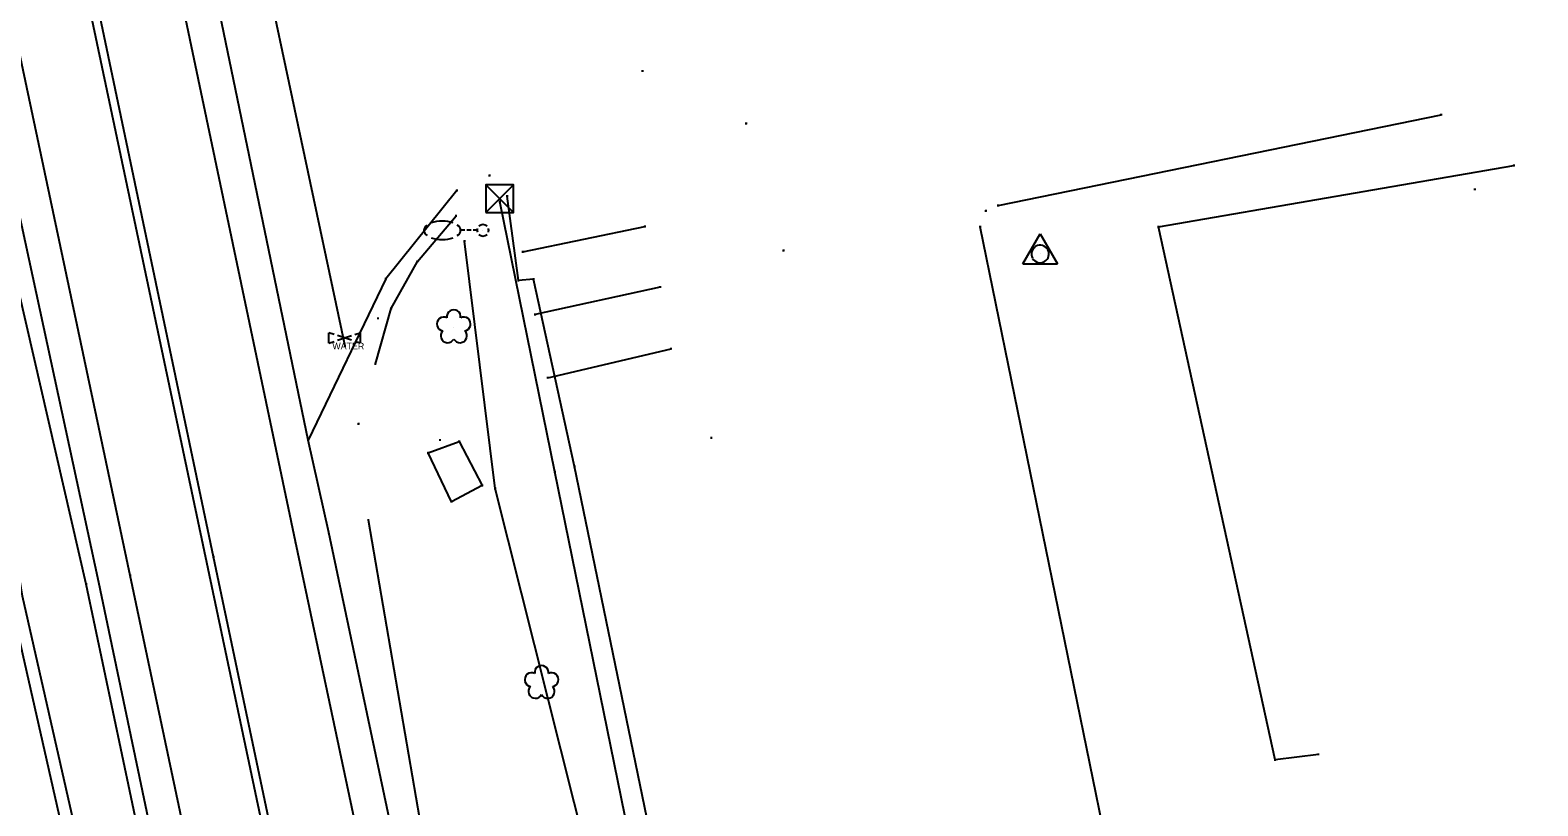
# Model space of a CAD drawing. Extents: x 1954856 to 2011933, y 399149 to 426294.
# Drawn here: x 2005902.3 to 2006119.2, y 403540.3 to 403651.8 of the extents above; entities that cross this region are included whole.
import ezdxf

# ---------------------------------------------------------------- set-up
doc = ezdxf.new("R2010")
doc.units = 0
for name, color, linetype in [('BankMent_ep', 7, 'Continuous'), ('BaselineSurvey', 7, 'Continuous'), ('Building_ep', 7, 'Continuous'), ('Driveway_ep', 7, 'Continuous'), ('Fence_ep', 7, 'Continuous'), ('Luminaire_ep', 7, 'Continuous'), ('MonumentIRC_ep', 7, 'Continuous'), ('MonumentPST_ep', 7, 'Continuous'), ('PavtAsphalt_ep', 7, 'Continuous'), ('PavtAsphaltCrown_ep', 7, 'Continuous'), ('PavtMisc_ep', 7, 'Continuous'), ('PMRK_ep', 7, 'Continuous'), ('PointLocator_ep', 7, 'Continuous'), ('ShldrPaved_ep', 7, 'Continuous'), ('Stairs_ep', 7, 'Continuous'), ('Tree_ep', 7, 'Continuous'), ('ValveWater_ep', 7, 'Continuous'), ('WaterB_ep', 7, 'Continuous')]:
    doc.layers.add(name, color=color, linetype=linetype)

msp = doc.modelspace()

# ---------------------------------------------------------------- linework, layer by layer
at = {"layer": 'BankMent_ep'}
for p, q in [((2005910.36, 403572.2), (2005893.93, 403643.41)), ((2005968.19, 403481.12), (2005950.95, 403581.41)), ((2005930.87, 403474.8), (2005910.36, 403572.2))]:
    msp.add_line(p, q, dxfattribs=at)
for points in [[(2006022.07, 402978.64), (2006021.6, 402982.93), (2006003.19, 403080.58), (2005983.54, 403176.28), (2005962.47, 403276.29), (2005940.44, 403373.6), (2005921.47, 403472.81), (2005899.51, 403569.73), (2005886.48, 403640.98)], [(2006026.18, 402980.46), (2006025.45, 402983.89), (2006004.8, 403080.94), (2005986.55, 403176.87), (2005964.79, 403276.97), (2005944.38, 403374.63), (2005923.28, 403472.99), (2005901.17, 403570.47), (2005889.78, 403641.66)], [(2006032.88, 403297.75), (2006007.75, 403389.93), (2005993.76, 403488.23), (2005969.18, 403585.92), (2005964.79, 403621.47)]]:
    msp.add_lwpolyline(points, dxfattribs=at)
at = {"layer": 'BaselineSurvey'}
msp.add_line((2006223.92, 402174.38), (2005094.48, 407516.05), dxfattribs=at)
msp.add_line((2006223.92, 402174.38), (2005094.48, 407516.05), dxfattribs=at)
at = {"layer": 'Building_ep'}
msp.add_lwpolyline([(2006087.61, 403547.72), (2006081.39, 403546.92), (2006064.61, 403623.54), (2006115.74, 403632.36)], dxfattribs=at)
at = {"layer": 'Driveway_ep'}
for p, q in [((2005963.68, 403628.76), (2005953.48, 403616.07)), ((2005972.53, 403615.83), (2005970.92, 403627.98)), ((2005953.48, 403616.07), (2005942.29, 403592.9)), ((2005974.72, 403616.02), (2005972.53, 403615.83)), ((2005980.62, 403589.11), (2005974.72, 403616.02)), ((2006000.9, 403490.61), (2005980.62, 403589.11))]:
    msp.add_line(p, q, dxfattribs=at)
at = {"layer": 'Fence_ep'}
msp.add_lwpolyline([(2005951.96, 403603.84), (2005954.23, 403611.8), (2005958.02, 403618.59), (2005963.56, 403625.11)], dxfattribs=at)
at = {"layer": 'Luminaire_ep'}
for p, q in [((2005964.81, 403623.05), (2005964.21, 403623.05)), ((2005965.71, 403623.05), (2005965.11, 403623.05)), ((2005966.61, 403623.05), (2005966.01, 403623.05)), ((2005967.43, 403623.05), (2005967.43, 403623.05))]:
    msp.add_line(p, q, dxfattribs=at)
for start, end in [(159.9115, 200.0885), (45, 135), (225, 315), (339.9115, 20.0885)]:
    msp.add_arc((2005967.43, 403623.05), 0.825, start, end, dxfattribs=at)
for start_param, end_param in [(4.075781, 5.348997), (5.668326, 6.898045), (2.526733, 3.756452), (0.934187, 2.207405)]:
    msp.add_ellipse((2005961.57, 403623.05), major_axis=(-2.64, 0), ratio=0.5, start_param=start_param, end_param=end_param, dxfattribs=at)
at = {"layer": 'MonumentIRC_ep'}
for p, q in [((2006045.09, 403618.21), (2006047.59, 403622.54)), ((2006047.59, 403622.54), (2006050.09, 403618.21)), ((2006045.09, 403618.21), (2006050.09, 403618.21)), ((2006047.59, 403619.65), (2006047.59, 403619.65))]:
    msp.add_line(p, q, dxfattribs=at)
msp.add_arc((2006047.59, 403619.65), 1.26, 209.9294, 209.03, dxfattribs=at)
at = {"layer": 'MonumentPST_ep'}
for p, q in [((2005967.84, 403629.6), (2005971.84, 403625.59)), ((2005967.84, 403625.59), (2005971.84, 403629.6)), ((2005969.84, 403627.6), (2005969.84, 403627.6))]:
    msp.add_line(p, q, dxfattribs=at)
msp.add_lwpolyline([(2005967.84, 403625.59), (2005971.84, 403625.59), (2005971.84, 403629.6), (2005967.84, 403629.6), (2005967.84, 403625.59)], dxfattribs=at)
at = {"layer": 'PavtAsphalt_ep'}
for p, q in [((2005916.68, 403573.45), (2005896.01, 403670.98)), ((2005937.3, 403476.2), (2005916.68, 403573.45))]:
    msp.add_line(p, q, dxfattribs=at)
msp.add_lwpolyline([(2006233.39, 402199.4), (2006231.31, 402208.78), (2006210.3, 402306.91), (2006189.73, 402404.41), (2006168.52, 402502.44), (2006147.45, 402600.55), (2006127, 402698.2), (2006106.48, 402795.48), (2006085.7, 402893.48), (2006064.78, 402991.32), (2006043.91, 403089.28), (2006023.05, 403187.5), (2006002.57, 403285.23), (2005981.7, 403382.7), (2005961.21, 403480.5), (2005940.45, 403578.3), (2005919.87, 403676.23), (2005898.84, 403774.26)], dxfattribs=at)
at = {"layer": 'PavtAsphaltCrown_ep'}
msp.add_lwpolyline([(2006221.58, 402197.04), (2006219.37, 402206.69), (2006198.42, 402304.43), (2006177.67, 402402.21), (2006156.49, 402500.14), (2006135.92, 402597.88), (2006115.39, 402695.49), (2006094.3, 402793.44), (2006073.8, 402891.43), (2006052.86, 402989.16), (2006032.08, 403086.96), (2006011.06, 403184.66), (2005990.58, 403282.63), (2005969.86, 403380.23), (2005949.3, 403478.33), (2005928.68, 403576.1), (2005908.1, 403674.03), (2005887.14, 403771.84)], dxfattribs=at)
at = {"layer": 'PavtMisc_ep'}
for p, q in [((2006041.53, 403626.6), (2006105.27, 403639.67)), ((2006041.53, 403626.6), (2006105.27, 403639.67)), ((2006058.94, 403525.92), (2006038.97, 403623.56)), ((2006058.94, 403525.92), (2006038.97, 403623.56))]:
    msp.add_line(p, q, dxfattribs=at)
at = {"layer": 'PMRK_ep'}
for points in [[(2005973.17, 403619.95), (2005990.73, 403623.59)], [(2005992.93, 403614.89), (2005974.93, 403610.93)], [(2005976.75, 403601.87), (2005994.49, 403606.03)]]:
    msp.add_lwpolyline(points, dxfattribs=at)
at = {"layer": 'PointLocator_ep'}
for p, q in [((2005990.5, 403645.95), (2005990.25, 403645.95)), ((2005990.37, 403645.83), (2005990.37, 403646.08)), ((2005990.37, 403645.95), (2005990.37, 403645.95)), ((2006105.39, 403639.67), (2006105.14, 403639.67)), ((2006105.27, 403639.54), (2006105.27, 403639.79)), ((2006105.27, 403639.67), (2006105.27, 403639.67)), ((2006005.42, 403638.39), (2006005.17, 403638.39)), ((2006005.29, 403638.27), (2006005.29, 403638.52)), ((2006005.29, 403638.39), (2006005.29, 403638.39)), ((2005968.39, 403630.79), (2005968.39, 403631.04)), ((2006115.86, 403632.36), (2006115.61, 403632.36)), ((2006115.74, 403632.23), (2006115.74, 403632.48)), ((2006115.74, 403632.36), (2006115.74, 403632.36)), ((2005963.81, 403628.76), (2005963.56, 403628.76)), ((2005963.68, 403628.64), (2005963.68, 403628.89)), ((2005963.68, 403628.76), (2005963.68, 403628.76)), ((2005968.52, 403630.91), (2005968.27, 403630.91)), ((2005968.39, 403630.91), (2005968.39, 403630.91)), ((2006110.26, 403628.92), (2006110.01, 403628.92)), ((2006110.13, 403628.8), (2006110.13, 403629.05)), ((2006110.13, 403628.92), (2006110.13, 403628.92)), ((2005970, 403627.19), (2005969.75, 403627.19)), ((2005969.88, 403627.07), (2005969.88, 403627.32)), ((2005969.88, 403627.19), (2005969.88, 403627.19)), ((2005971.05, 403627.98), (2005970.8, 403627.98)), ((2005970.92, 403627.85), (2005970.92, 403628.1)), ((2005970.92, 403627.98), (2005970.92, 403627.98)), ((2006041.65, 403626.6), (2006041.4, 403626.6)), ((2006041.53, 403626.47), (2006041.53, 403626.72)), ((2006041.53, 403626.6), (2006041.53, 403626.6)), ((2005963.69, 403625.11), (2005963.44, 403625.11)), ((2005963.56, 403624.99), (2005963.56, 403625.24)), ((2005963.56, 403625.11), (2005963.56, 403625.11)), ((2006039.91, 403625.84), (2006039.66, 403625.84)), ((2006039.79, 403625.72), (2006039.79, 403625.97)), ((2006039.79, 403625.84), (2006039.79, 403625.84)), ((2005990.86, 403623.59), (2005990.61, 403623.59)), ((2005990.73, 403623.46), (2005990.73, 403623.71)), ((2005990.73, 403623.59), (2005990.73, 403623.59)), ((2006039.09, 403623.56), (2006038.84, 403623.56)), ((2006038.97, 403623.44), (2006038.97, 403623.69)), ((2006038.97, 403623.56), (2006038.97, 403623.56)), ((2006064.73, 403623.54), (2006064.48, 403623.54)), ((2006064.61, 403623.42), (2006064.61, 403623.67)), ((2006064.61, 403623.54), (2006064.61, 403623.54)), ((2005964.92, 403621.47), (2005964.67, 403621.47)), ((2005964.79, 403621.34), (2005964.79, 403621.59)), ((2005964.79, 403621.47), (2005964.79, 403621.47)), ((2006010.8, 403620.13), (2006010.55, 403620.13)), ((2006010.67, 403620), (2006010.67, 403620.25)), ((2006010.67, 403620.13), (2006010.67, 403620.13)), ((2005958.14, 403618.59), (2005957.89, 403618.59)), ((2005958.02, 403618.46), (2005958.02, 403618.71)), ((2005958.02, 403618.59), (2005958.02, 403618.59)), ((2005973.29, 403619.95), (2005973.04, 403619.95)), ((2005973.17, 403619.83), (2005973.17, 403620.08)), ((2005973.17, 403619.95), (2005973.17, 403619.95)), ((2005953.61, 403616.07), (2005953.36, 403616.07)), ((2005953.48, 403615.95), (2005953.48, 403616.2)), ((2005953.48, 403616.07), (2005953.48, 403616.07)), ((2005972.65, 403615.83), (2005972.4, 403615.83)), ((2005972.53, 403615.71), (2005972.53, 403615.96)), ((2005972.53, 403615.83), (2005972.53, 403615.83)), ((2005974.85, 403616.02), (2005974.6, 403616.02)), ((2005974.72, 403615.89), (2005974.72, 403616.14)), ((2005974.72, 403616.02), (2005974.72, 403616.02)), ((2005993.05, 403614.89), (2005992.8, 403614.89)), ((2005992.93, 403614.77), (2005992.93, 403615.02)), ((2005992.93, 403614.89), (2005992.93, 403614.89)), ((2005954.35, 403611.8), (2005954.1, 403611.8)), ((2005954.23, 403611.68), (2005954.23, 403611.93)), ((2005954.23, 403611.8), (2005954.23, 403611.8)), ((2005952.46, 403610.39), (2005952.21, 403610.39)), ((2005952.34, 403610.26), (2005952.34, 403610.51)), ((2005952.34, 403610.39), (2005952.34, 403610.39)), ((2005975.06, 403610.93), (2005974.81, 403610.93)), ((2005974.93, 403610.8), (2005974.93, 403611.05)), ((2005974.93, 403610.93), (2005974.93, 403610.93)), ((2005947.72, 403606.4), (2005947.47, 403606.4)), ((2005947.59, 403606.28), (2005947.59, 403606.53)), ((2005947.59, 403606.4), (2005947.59, 403606.4)), ((2005994.62, 403606.03), (2005994.37, 403606.03)), ((2005994.49, 403605.91), (2005994.49, 403606.16)), ((2005994.49, 403606.03), (2005994.49, 403606.03)), ((2005952.08, 403603.84), (2005951.83, 403603.84)), ((2005951.96, 403603.71), (2005951.96, 403603.96)), ((2005951.96, 403603.84), (2005951.96, 403603.84)), ((2005976.88, 403601.87), (2005976.63, 403601.87)), ((2005976.75, 403601.74), (2005976.75, 403601.99)), ((2005976.75, 403601.87), (2005976.75, 403601.87)), ((2005949.66, 403595.22), (2005949.41, 403595.22)), ((2005949.54, 403595.1), (2005949.54, 403595.35)), ((2005949.54, 403595.22), (2005949.54, 403595.22)), ((2005942.41, 403592.9), (2005942.16, 403592.9)), ((2005942.29, 403592.77), (2005942.29, 403593.02)), ((2005942.29, 403592.9), (2005942.29, 403592.9)), ((2005961.39, 403592.9), (2005961.14, 403592.9)), ((2005961.27, 403592.77), (2005961.27, 403593.02)), ((2005961.27, 403592.9), (2005961.27, 403592.9)), ((2005964.15, 403592.71), (2005963.9, 403592.71)), ((2005964.02, 403592.59), (2005964.02, 403592.84)), ((2005964.02, 403592.71), (2005964.02, 403592.71)), ((2006000.42, 403593.2), (2006000.17, 403593.2)), ((2006000.3, 403593.07), (2006000.3, 403593.32)), ((2006000.3, 403593.2), (2006000.3, 403593.2)), ((2005959.68, 403591.06), (2005959.43, 403591.06)), ((2005959.55, 403590.93), (2005959.55, 403591.18)), ((2005959.55, 403591.06), (2005959.55, 403591.06)), ((2005977.91, 403588.32), (2005977.66, 403588.32)), ((2005977.79, 403588.2), (2005977.79, 403588.45)), ((2005977.79, 403588.32), (2005977.79, 403588.32)), ((2005980.74, 403589.11), (2005980.49, 403589.11)), ((2005980.62, 403588.98), (2005980.62, 403589.23)), ((2005980.62, 403589.11), (2005980.62, 403589.11)), ((2005967.46, 403586.35), (2005967.21, 403586.35)), ((2005967.33, 403586.22), (2005967.33, 403586.47)), ((2005967.33, 403586.35), (2005967.33, 403586.35)), ((2005969.31, 403585.92), (2005969.06, 403585.92)), ((2005969.18, 403585.8), (2005969.18, 403586.05)), ((2005969.18, 403585.92), (2005969.18, 403585.92)), ((2005963.04, 403584.03), (2005962.79, 403584.03)), ((2005962.92, 403583.91), (2005962.92, 403584.16)), ((2005962.92, 403584.03), (2005962.92, 403584.03)), ((2005951.07, 403581.41), (2005950.82, 403581.41)), ((2005950.95, 403581.28), (2005950.95, 403581.53)), ((2005950.95, 403581.41), (2005950.95, 403581.41)), ((2005945.37, 403579.6), (2005945.12, 403579.6)), ((2005945.25, 403579.48), (2005945.25, 403579.73)), ((2005945.25, 403579.6), (2005945.25, 403579.6)), ((2005940.57, 403578.3), (2005940.32, 403578.3)), ((2005940.45, 403578.18), (2005940.45, 403578.43)), ((2005940.45, 403578.3), (2005940.45, 403578.3)), ((2005928.8, 403576.1), (2005928.55, 403576.1)), ((2005928.68, 403575.98), (2005928.68, 403576.23)), ((2005928.68, 403576.1), (2005928.68, 403576.1)), ((2005912.29, 403572.44), (2005912.04, 403572.44)), ((2005912.16, 403572.32), (2005912.16, 403572.57)), ((2005912.16, 403572.44), (2005912.16, 403572.44)), ((2005916.81, 403573.45), (2005916.56, 403573.45)), ((2005916.68, 403573.33), (2005916.68, 403573.58)), ((2005916.68, 403573.45), (2005916.68, 403573.45)), ((2005910.49, 403572.2), (2005910.24, 403572.2)), ((2005910.36, 403572.08), (2005910.36, 403572.33)), ((2005910.36, 403572.2), (2005910.36, 403572.2)), ((2006081.52, 403546.92), (2006081.27, 403546.92)), ((2006081.39, 403546.79), (2006081.39, 403547.04)), ((2006081.39, 403546.92), (2006081.39, 403546.92)), ((2006087.73, 403547.72), (2006087.48, 403547.72)), ((2006087.61, 403547.6), (2006087.61, 403547.85)), ((2006087.61, 403547.72), (2006087.61, 403547.72))]:
    msp.add_line(p, q, dxfattribs=at)
at = {"layer": 'ShldrPaved_ep'}
for p, q in [((2005912.16, 403572.44), (2005895.26, 403650.68)), ((2005932.63, 403474.96), (2005912.16, 403572.44))]:
    msp.add_line(p, q, dxfattribs=at)
msp.add_lwpolyline([(2006236.97, 402200.29), (2006234.96, 402209.44), (2006223.13, 402265.91), (2006222.91, 402271.95), (2006207.49, 402343.57), (2006194.34, 402405.59), (2006173.46, 402503.37), (2006152.82, 402601.72), (2006132.25, 402699.3), (2006111.09, 402796.88), (2006090.39, 402894.56), (2006069.53, 402992.45), (2006048.7, 403090.06), (2006039.79, 403131.91), (2006031.78, 403169.97), (2006021.65, 403217.64), (2006000.24, 403320.06), (2005986.36, 403383.8), (2005966.07, 403481.27), (2005945.25, 403579.6), (2005942.29, 403592.9), (2005924.79, 403677.39), (2005916.05, 403717.64), (2005903.42, 403775.17)], dxfattribs=at)
at = {"layer": 'Stairs_ep'}
msp.add_lwpolyline([(2006039.43, 403302.93), (2006038.41, 403295.5), (2006037.94, 403295.31), (2006017.63, 403392.22), (2005997.89, 403489.66), (2005977.79, 403588.32), (2005969.88, 403627.19)], dxfattribs=at)
msp.add_lwpolyline([(2005967.33, 403586.35), (2005962.92, 403584.03), (2005959.55, 403591.06), (2005964.02, 403592.71)], close=True, dxfattribs=at)
at = {"layer": 'Tree_ep'}
for p, q in [((2005963.23, 403609.12), (2005963.23, 403609.12)), ((2005975.86, 403557.99), (2005975.86, 403557.99))]:
    msp.add_line(p, q, dxfattribs=at)
for centre, start, end in [((2005963.23, 403610.62), 352.1546, 187.8454), ((2005961.81, 403609.58), 64.1546, 259.8454), ((2005964.66, 403609.58), 280.1546, 115.8454), ((2005962.35, 403607.9), 136.1546, 331.8454), ((2005964.12, 403607.9), 208.1546, 43.8454), ((2005974.43, 403558.46), 64.1546, 259.8454), ((2005975.86, 403559.49), 352.1546, 187.8454), ((2005977.29, 403558.46), 280.1546, 115.8454), ((2005974.98, 403556.78), 136.1546, 331.8454), ((2005976.74, 403556.78), 208.1546, 43.8454)]:
    msp.add_arc(centre, 1, start, end, dxfattribs=at)
at = {"layer": 'ValveWater_ep'}
for p, q in [((2005946.01, 403608.08), (2005945.26, 403608.33)), ((2005945.26, 403606.83), (2005945.26, 403608.33)), ((2005945.26, 403606.83), (2005946.01, 403607.08)), ((2005948.51, 403607.25), (2005946.51, 403607.91)), ((2005946.51, 403607.25), (2005948.51, 403607.91)), ((2005947.51, 403607.58), (2005947.51, 403607.58)), ((2005949.01, 403608.08), (2005949.76, 403608.33)), ((2005949.76, 403606.83), (2005949.01, 403607.08)), ((2005949.76, 403608.33), (2005949.76, 403606.83))]:
    msp.add_line(p, q, dxfattribs=at)
at = {"layer": 'WaterB_ep'}
msp.add_lwpolyline([(2005947.59, 403606.4), (2005935.06, 403665.48), (2005924.61, 403663.68)], dxfattribs=at)
msp.add_lwpolyline([(2005947.59, 403606.4), (2005935.06, 403665.48), (2005924.61, 403663.68)], dxfattribs=at)

# ---------------------------------------------------------------- texts
at = {"layer": 'ValveWater_ep'}
msp.add_text('WATER', height=0.95, dxfattribs=at).set_placement((2005945.77, 403605.94))

doc.saveas('drawing.dxf')
